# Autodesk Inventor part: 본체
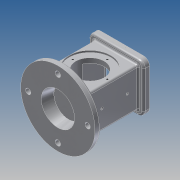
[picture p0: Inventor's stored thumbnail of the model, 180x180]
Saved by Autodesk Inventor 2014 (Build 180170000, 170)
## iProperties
Created: 2018-10
Part Number: 본체
Material: 알루미늄 6061
Document SubType Name: Modeling
Designer: kb542
Density: 2.71 g/cm^3
Appearance: 알루미늄 - 평지
Mass: 985.731 g
Surface Area: 750.08 cm^2
Volume: 363.738 cm^3
Author: kb542
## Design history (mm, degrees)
sketch "스케치1"
  geometry: C1 r 62.5 at (0, 0); 1 further point
  constraints: 1 centre point, 1 coincident
  dimensions: "d0" = 125 diameter of C1
extrude "돌출1" new body sketch "스케치1" distance "d1" = 10; taper "d2" = 0 deg
sketch "스케치2"
  geometry: L1 (-37, 33)-(37, 33); L2 (37, 33)-(37, -33); L3 (37, -33)-(-37, -33); L4 (-37, -33)-(-37, 33); C1 r 62.5 at (0, 0) reference
  constraints: 8 end point, 2 parallel, 1 horizontal, 1 perpendicular
  dimensions: "d3" = 74 distance of L1.start L1.end; "d4" = 37 distance from line of L2 C1.centre; "d5" = 66 distance between parallel lines of L3 L1; "d6" = 33 distance from line of C1.centre L3
extrude "돌출2" join sketch "스케치2" distance "d7" = 88; taper "d8" = 0 deg
sketch "스케치3"
  geometry: L1 (-46, 41)-(46, 41); L2 (46, 41)-(46, -41); L3 (46, -41)-(-46, -41); L4 (-46, -41)-(-46, 41); 1 further point
  constraints: 8 end point, 2 parallel, 1 horizontal, 1 perpendicular
  dimensions: "d9" = 92 distance of L1.start L1.end; "d10" = 46 distance from line of point (0, 0) L2; "d11" = 82 distance of L1.end L2.end; "d12" = 41 distance from line of L3 point (0, 0)
extrude "돌출3" join sketch "스케치3" distance "d13" = 10; taper "d14" = 0 deg
sketch "스케치4"
  geometry: L1 (-62.5, 0)-(62.5, 0) reference; L2 (-28, 0)-(-24.826, 18); L3 (-24.826, 18)-(0, 18); L4 (0, 18)-(0, 0); L5 (-28, 0)-(0, 0); 1 further point
  constraints: 8 end point, 2 perpendicular, 1 midpoint, 1 parallel, 1 point on line
  dimensions: "d15" = 0 distance from line of point (0, 0) L4; "d16" = 56 diameter of L2.start L4; "d17" = 18 distance between parallel lines of L3 L1; "d18" = 80 deg angle of L1 L2
revolve "회전1" sketch "스케치4" stored, may be unused: angle "d19" = 90 deg
sketch "스케치5"
  geometry: L1 (-22, 22)-(22, 22); L2 (22, 22)-(22, -22); L3 (22, -22)-(-22, -22); L4 (-22, -22)-(-22, 22); 1 further point
  constraints: 8 end point, 2 parallel, 1 horizontal, 1 perpendicular
  dimensions: "d20" = 44 distance of L1.start L1.end; "d21" = 22 distance from line of point (0, 0) L4; "d22" = 44 distance between parallel lines of L3 L1; "d23" = 22 distance from line of L1 point (0, 0)
extrude "돌출4" cut sketch "스케치5" distance "d24" = 82; taper "d25" = 0 deg
sketch "스케치6"
  geometry: L1 (-22, -22)-(-22, 22) reference; L2 (-22, 22)-(22, 22) reference; L3 (22, 22)-(22, -22) reference; L4 (22, -22)-(-22, -22) reference; L5 (-26, -26)-(26, -26); L6 (26, -26)-(26, 26); L7 (26, 26)-(-26, 26); L8 (-26, 26)-(-26, -26); L9 (-26, -26)-(26, 26); L10 (26, -26)-(-26, 26); 1 further point
  constraints: 12 end point, 2 midpoint, 2 parallel, 1 horizontal, 1 perpendicular
  dimensions: "d26" = 52 distance of L6.end L7.end; "d27" = 52 distance of L5.end L6.end
extrude "돌출5" cut sketch "스케치6" distance "d28" = 8; taper "d29" = 0 deg
sketch "스케치8"
  geometry: L1 (65, -10)-(9, -10) reference; 2 further points
  constraints: 1 vertical alignment
  dimensions: "d31" = 54 distance from line of point (37, 44) L1
hole "구멍1" sketch "스케치8" at (37, 44) diameter "d32" = 48; stored, may be unused: countersink angle "d36" = 90 deg, drill point angle "d38" = 118 deg; dims "d33" = 6, "d34" = 70, "d35" = 3, "d37" = 8
sketch "스케치9"
  geometry: C1 r 35 at (0, 0) reference; 2 further points
  constraints: 1 vertical alignment
  dimensions: "d39" = 29 distance of point (0, 29) C1.centre
sketch "스케치10"
  geometry: C1 r 62.5 at (0, 0) reference; 1 further point
  constraints: 1 horizontal alignment
  dimensions: "d40" = 50 distance of C1.centre point (-50, 0)
hole "구멍2" sketch "스케치10" at (-50, 0) diameter "d41" = 9; stored, may be unused: countersink angle "d45" = 82 deg, drill point angle "d47" = 118 deg; dims "d42" = 8.608, "d43" = 19.05, "d44" = 4.775, "d46" = 6
fillet "모깎기1" dims "d51" = 3
fillet "모깎기2" dims "d52" = 3
fillet "모깎기3" dims "d53" = 3
fillet "모깎기4" dims "d54" = 10
fillet "모깎기5" dims "d55" = 3
hole "구멍3" sketch "스케치9" diameter "d56" = 3.242; stored, may be unused: countersink angle "d60" = 82 deg, drill point angle "d62" = 118 deg; dims "d57" = 4, "d58" = 19.05, "d59" = 4.775, "d61" = 6
sketch "스케치11"
  geometry: A1 r 10 centre (-36, -31) between (-46, -31) and (-36, -41) reference; 2 further points
  constraints: 1 coincident
hole "구멍4" sketch "스케치11" at (-36, -31) diameter "d66" = 3.242; stored, may be unused: countersink angle "d70" = 82 deg, drill point angle "d72" = 118 deg; dims "d67" = 4, "d68" = 19.05, "d69" = 4.775, "d71" = 6
sketch "스케치12"
  geometry: L1 (-32.5, -13)-(92.5, -13) reference; 2 further points
  constraints: 1 vertical alignment
  dimensions: "d79" = 37 distance from line of point (30, 24) L1
hole "구멍5" sketch "스케치12" at (30, 24) diameter "d80" = 4.134; stored, may be unused: countersink angle "d84" = 82 deg, drill point angle "d86" = 118 deg; dims "d81" = 4, "d82" = 19.05, "d83" = 4.775, "d85" = 20
sketch "스케치13"
  geometry: L1 (0, 0)-(72, 0) reference; L2 (-10, 0)-(-10, -7) reference; 2 further points
  constraints: 1 other
  dimensions: "d90" = 46 distance from line of point (36, -4) L2; "d91" = 4 distance from line of L1 point (36, -4)
feature "엠보싱1" sketch "스케치13" dims "d2" = 0, "d92" = 0.5, "d93" = 0
chamfer "모따기1" distance "d94" = 1; stored, may be unused: second distance "d95" = 2, angle "d96" = 45 deg
node "솔리드1"
mirror "대칭1"
pattern_circular "원형 패턴1" dims angle "d49" = 360 deg
pattern_circular "원형 패턴2" dims angle "d64" = 360 deg
mirror "대칭2"
pattern_linear "직사각형 패턴1" dims "d75" = 72, "d78" = 62
pattern_linear "직사각형 패턴2" dims "d89" = 43
